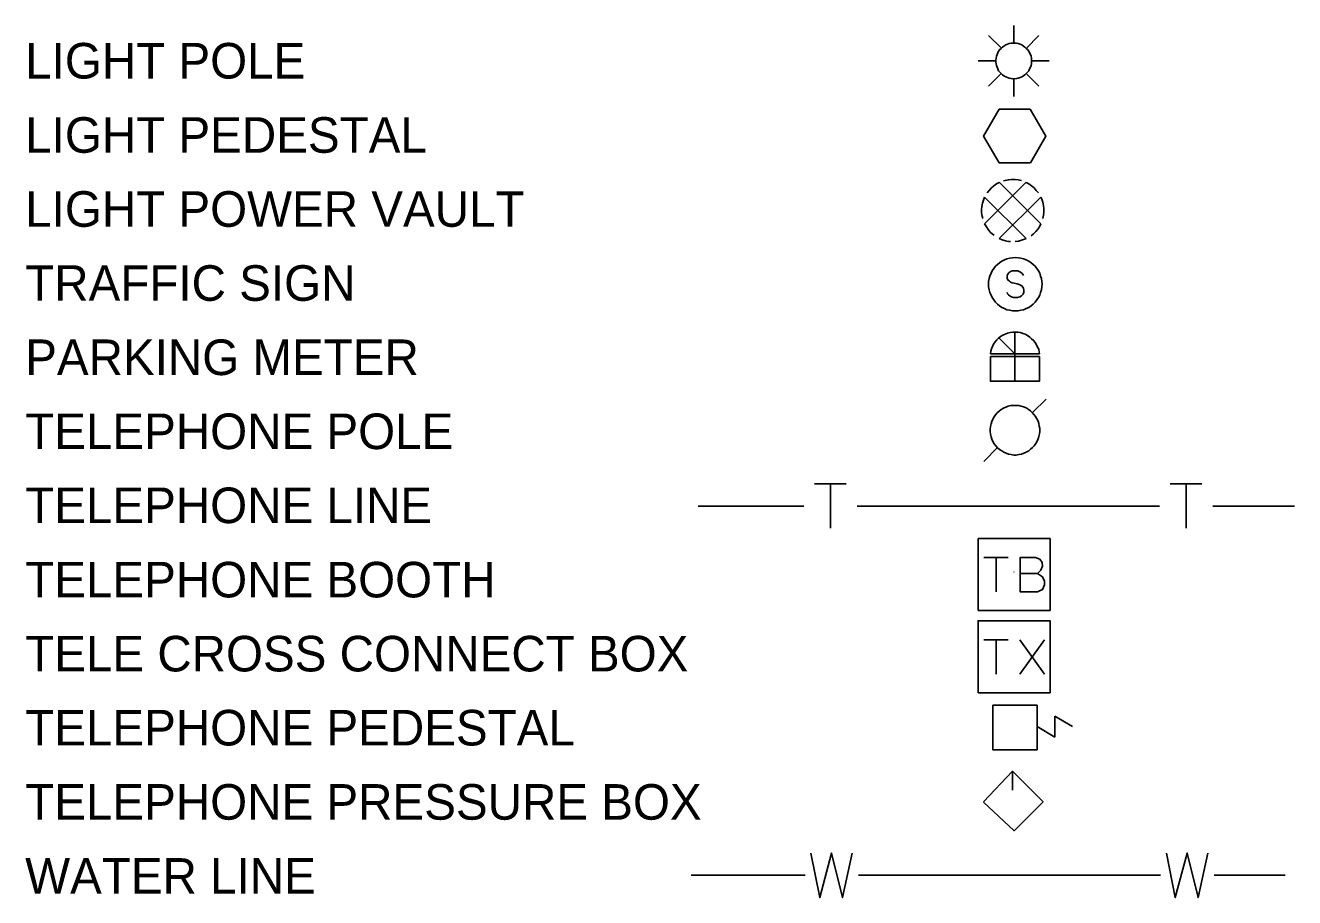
# Model space of a CAD drawing. Extents: x -1.93 to 2.83, y -1.79 to 1.85.
# Drawn here: x 0.5147 to 0.7634, y 1.1397 to 1.3106 of the extents above; entities that cross this region are included whole.
import ezdxf

# ---------------------------------------------------------------- set-up
doc = ezdxf.new("R2010")
doc.units = 0
doc.layers.add('Legend', color=7, linetype='Continuous')

msp = doc.modelspace()

# ---------------------------------------------------------------- linework, layer by layer
at = {"layer": 'Legend'}
for p, q in [((0.64654, 1.21642), (0.66721, 1.21642)), ((0.67766, 1.21642), (0.73691, 1.21642)), ((0.74733, 1.21642), (0.76337, 1.21642)), ((0.64512, 1.1441), (0.66746, 1.1441)), ((0.67791, 1.1441), (0.73712, 1.1441)), ((0.74758, 1.1441), (0.76154, 1.1441))]:
    msp.add_line(p, q, dxfattribs=at)
for points in [[(0.70835, 1.30711), (0.70835, 1.31057)], [(0.70589, 1.30615), (0.70339, 1.30857)], [(0.71081, 1.30607), (0.71327, 1.30857)], [(0.71081, 1.30607), (0.71052, 1.30632), (0.71023, 1.30653), (0.70993, 1.30674), (0.7096, 1.30686), (0.70923, 1.30699), (0.70889, 1.30707), (0.70852, 1.30711), (0.70814, 1.30711), (0.70781, 1.30707), (0.70743, 1.30699), (0.7071, 1.30686), (0.70677, 1.30674), (0.70643, 1.30653), (0.70614, 1.30632), (0.70585, 1.30607), (0.70564, 1.30582), (0.70539, 1.30553), (0.70523, 1.30519), (0.7051, 1.30486), (0.70498, 1.30453), (0.70489, 1.30415), (0.70485, 1.30378), (0.70485, 1.30344), (0.70489, 1.30307), (0.70498, 1.30269), (0.7051, 1.30236), (0.70523, 1.30203), (0.70539, 1.30169), (0.70564, 1.3014), (0.70585, 1.30115), (0.70614, 1.3009), (0.70643, 1.30069), (0.70677, 1.30049), (0.7071, 1.30036), (0.70743, 1.30024), (0.70781, 1.30015), (0.70814, 1.30011), (0.70852, 1.30011), (0.70889, 1.30015), (0.70923, 1.30024), (0.7096, 1.30036), (0.70993, 1.30049), (0.71023, 1.30069), (0.71052, 1.3009), (0.71081, 1.30115), (0.71106, 1.3014), (0.71127, 1.30169), (0.71143, 1.30203), (0.7116, 1.30236), (0.71173, 1.30269), (0.71181, 1.30307), (0.71181, 1.30344), (0.71181, 1.30378), (0.71181, 1.30415), (0.71173, 1.30453), (0.7116, 1.30486), (0.71143, 1.30519), (0.71127, 1.30553), (0.71106, 1.30582), (0.71081, 1.30607)], [(0.70139, 1.30361), (0.70489, 1.30361)], [(0.71181, 1.30361), (0.71531, 1.30361)], [(0.70589, 1.30115), (0.70339, 1.29869)], [(0.71081, 1.30115), (0.71327, 1.29869)], [(0.70835, 1.29665), (0.70835, 1.30015)], [(0.70552, 1.29417), (0.71156, 1.29417), (0.71464, 1.28887), (0.7116, 1.28362), (0.70552, 1.28362), (0.70243, 1.28887), (0.70552, 1.29417)], [(0.71081, 1.27984), (0.70264, 1.27167)], [(0.70552, 1.2798), (0.70498, 1.27951), (0.70443, 1.27913), (0.70398, 1.27872), (0.70352, 1.27826), (0.70314, 1.27776)], [(0.70552, 1.27984), (0.71368, 1.27167)], [(0.70985, 1.28017), (0.70923, 1.2803), (0.7086, 1.28038), (0.70793, 1.28038), (0.70731, 1.28034), (0.70668, 1.28022), (0.70631, 1.28013)], [(0.71318, 1.27776), (0.71277, 1.27826), (0.71235, 1.27872), (0.71185, 1.27913), (0.71131, 1.27951), (0.71077, 1.2798)], [(0.70264, 1.27692), (0.70239, 1.27634), (0.70223, 1.27572), (0.7021, 1.27509), (0.70206, 1.27447), (0.70206, 1.27384), (0.70214, 1.27322), (0.70227, 1.27272)], [(0.70264, 1.27692), (0.71081, 1.2688)], [(0.71368, 1.27692), (0.70552, 1.2688)], [(0.71406, 1.27276), (0.71418, 1.27338), (0.71423, 1.27401), (0.71423, 1.27463), (0.71418, 1.2753), (0.71402, 1.27592), (0.71385, 1.27651), (0.71364, 1.27692)], [(0.70264, 1.27167), (0.70298, 1.27109), (0.70331, 1.27059), (0.70373, 1.27009), (0.70418, 1.26967), (0.70448, 1.26947)], [(0.71173, 1.26938), (0.71223, 1.26976), (0.71268, 1.27022), (0.7131, 1.27072), (0.71343, 1.27126), (0.71364, 1.27167)], [(0.70552, 1.2688), (0.7061, 1.26855), (0.70673, 1.26838), (0.70735, 1.26826), (0.70768, 1.26822)], [(0.70864, 1.26822), (0.70927, 1.2683), (0.70989, 1.26847), (0.71048, 1.26867), (0.71077, 1.2688)], [(0.70864, 1.26509), (0.7081, 1.26505), (0.70756, 1.26497), (0.70702, 1.26484), (0.70652, 1.26463), (0.70602, 1.26438), (0.70556, 1.26409), (0.70514, 1.26376), (0.70477, 1.26338), (0.70443, 1.26292), (0.70414, 1.26247), (0.70389, 1.26201), (0.70368, 1.26147), (0.70356, 1.26097), (0.70343, 1.26042), (0.70343, 1.25988), (0.70343, 1.25934), (0.70356, 1.2588), (0.70368, 1.25826), (0.70389, 1.25776), (0.70414, 1.25726), (0.70443, 1.2568), (0.70477, 1.25638), (0.70514, 1.25597), (0.70556, 1.25563), (0.70602, 1.25534), (0.70652, 1.25509), (0.70702, 1.25488), (0.70756, 1.25476), (0.7081, 1.25467), (0.70864, 1.25463), (0.70918, 1.25467), (0.70973, 1.25476), (0.71027, 1.25488), (0.71077, 1.25509), (0.71127, 1.25534), (0.71173, 1.25563), (0.71214, 1.25597), (0.71252, 1.25638), (0.71289, 1.2568), (0.71318, 1.25726), (0.71343, 1.25776), (0.7136, 1.25826), (0.71377, 1.2588), (0.71385, 1.25934), (0.71389, 1.25988), (0.71385, 1.26042), (0.71377, 1.26097), (0.7136, 1.26147), (0.71343, 1.26201), (0.71318, 1.26247), (0.71289, 1.26292), (0.71252, 1.26338), (0.71214, 1.26376), (0.71173, 1.26409), (0.71127, 1.26438), (0.71077, 1.26463), (0.71027, 1.26484), (0.70973, 1.26497), (0.70918, 1.26505), (0.70864, 1.26509)], [(0.71023, 1.26155), (0.71018, 1.26172), (0.70998, 1.26197), (0.70964, 1.26226), (0.70914, 1.26247), (0.70877, 1.26251), (0.70835, 1.26251), (0.70806, 1.26247), (0.70768, 1.26234), (0.70739, 1.26213), (0.70714, 1.2618), (0.70706, 1.26142), (0.70706, 1.26105), (0.70718, 1.26072), (0.70752, 1.26047), (0.70773, 1.2603), (0.70806, 1.26017), (0.70843, 1.26005), (0.70902, 1.25992), (0.70943, 1.2598), (0.70993, 1.25955), (0.71023, 1.25909), (0.71031, 1.25867), (0.71031, 1.2583), (0.71018, 1.25792), (0.70985, 1.25763), (0.70952, 1.25742), (0.70906, 1.2573), (0.70873, 1.25726), (0.70831, 1.2573), (0.70789, 1.25738), (0.70764, 1.25755), (0.70731, 1.2578), (0.70714, 1.25797), (0.70706, 1.25822)], [(0.70377, 1.24624), (0.70385, 1.24674), (0.70398, 1.2472), (0.70418, 1.2477), (0.70439, 1.24812), (0.70468, 1.24857), (0.70502, 1.24895), (0.70539, 1.24928), (0.70577, 1.24962), (0.70623, 1.24991), (0.70668, 1.25012), (0.70714, 1.25028), (0.70764, 1.25041), (0.70814, 1.25049), (0.70864, 1.25049), (0.70914, 1.25049), (0.70964, 1.25041), (0.71014, 1.25024), (0.7106, 1.25007), (0.71106, 1.24982), (0.71148, 1.24953), (0.71185, 1.2492), (0.71223, 1.24887), (0.71252, 1.24845), (0.71281, 1.24803), (0.71302, 1.24757), (0.71323, 1.24712), (0.71335, 1.24662), (0.71339, 1.24624)], [(0.70856, 1.24624), (0.70543, 1.24937)], [(0.70856, 1.24093), (0.70856, 1.25049)], [(0.70377, 1.24624), (0.71339, 1.24624)], [(0.70377, 1.2457), (0.70377, 1.24087), (0.71339, 1.24087), (0.71339, 1.2457), (0.70377, 1.2457)], [(0.71198, 1.23475), (0.7116, 1.23509), (0.71118, 1.23538), (0.71077, 1.23563), (0.71027, 1.23584), (0.70981, 1.23596), (0.70931, 1.23609), (0.70881, 1.23613), (0.70831, 1.23613), (0.70777, 1.23609), (0.70727, 1.23596), (0.70681, 1.23579), (0.70635, 1.23559), (0.70589, 1.23534), (0.70548, 1.23504), (0.7051, 1.23467), (0.70477, 1.23429), (0.70448, 1.23388), (0.70423, 1.23346), (0.70402, 1.233), (0.70389, 1.2325), (0.70377, 1.232), (0.70373, 1.2315), (0.70373, 1.231), (0.70377, 1.2305), (0.70389, 1.23), (0.70406, 1.2295), (0.70427, 1.22904), (0.70452, 1.22863), (0.70481, 1.22821), (0.70518, 1.22784), (0.70556, 1.2275), (0.70598, 1.22721), (0.70639, 1.22696), (0.70685, 1.22675), (0.70735, 1.22659), (0.70785, 1.2265), (0.70835, 1.22642), (0.70885, 1.22642), (0.70935, 1.2265), (0.70985, 1.22659), (0.71035, 1.22675), (0.71081, 1.22696), (0.71127, 1.22721), (0.71164, 1.22754), (0.71202, 1.22788), (0.71235, 1.22825), (0.71268, 1.22867), (0.71293, 1.22913), (0.7131, 1.22959), (0.71327, 1.23004), (0.71339, 1.23054), (0.71343, 1.23104), (0.71343, 1.23159), (0.71335, 1.23209), (0.71327, 1.23259), (0.7131, 1.23304), (0.71289, 1.2335), (0.71264, 1.23396), (0.71231, 1.23438), (0.71198, 1.23475)], [(0.71468, 1.23738), (0.71202, 1.23475)], [(0.7051, 1.22784), (0.70248, 1.22517)], [(0.67244, 1.21209), (0.67244, 1.2208), (0.66929, 1.2208)], [(0.67244, 1.2208), (0.67553, 1.2208)], [(0.74211, 1.21209), (0.74211, 1.2208), (0.73896, 1.2208)], [(0.74211, 1.2208), (0.7452, 1.2208)], [(0.70139, 1.19597), (0.70139, 1.21005), (0.71548, 1.21005), (0.71548, 1.19597), (0.70139, 1.19597)], [(0.70493, 1.19964), (0.70493, 1.20634), (0.70248, 1.20634)], [(0.70493, 1.20634), (0.70727, 1.20634)], [(0.71298, 1.20322), (0.71364, 1.20384), (0.71398, 1.20464), (0.71389, 1.20539), (0.71343, 1.20601), (0.71264, 1.20634), (0.7096, 1.20634), (0.7096, 1.19964), (0.71298, 1.19964), (0.71398, 1.20005), (0.71439, 1.20097), (0.71439, 1.20172), (0.71398, 1.20255), (0.71298, 1.20322), (0.7096, 1.20322)], [(0.70135, 1.17985), (0.70135, 1.19397), (0.71548, 1.19397), (0.71548, 1.17985), (0.70135, 1.17985)], [(0.70489, 1.18352), (0.70489, 1.19022), (0.70248, 1.19022)], [(0.70489, 1.19022), (0.70723, 1.19022)], [(0.70956, 1.19022), (0.71435, 1.18352)], [(0.70956, 1.18352), (0.71435, 1.19022)], [(0.70423, 1.17741), (0.71293, 1.17741)], [(0.70423, 1.17741), (0.70423, 1.1687), (0.71293, 1.1687)], [(0.71293, 1.17741), (0.71293, 1.1687)], [(0.71639, 1.17524), (0.71639, 1.17116)], [(0.71985, 1.17324), (0.71639, 1.17524)], [(0.71639, 1.17116), (0.71293, 1.17324)], [(0.70239, 1.15848), (0.7081, 1.16448), (0.7141, 1.15848), (0.70843, 1.15281), (0.70239, 1.15844)], [(0.7081, 1.16448), (0.7081, 1.16077)], [(0.66862, 1.14844), (0.67034, 1.13973), (0.67267, 1.14844), (0.67479, 1.13973), (0.67671, 1.14844)], [(0.73829, 1.14844), (0.74, 1.13973), (0.74234, 1.14844), (0.74446, 1.13973), (0.74638, 1.14844)]]:
    msp.add_lwpolyline(points, dxfattribs=at)
msp.add_circle((0.70842, 1.20353), 0.000000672, dxfattribs=at)

# ---------------------------------------------------------------- texts
for s, height, p in [('LIGHT POLE', 0.006967, (0.51467, 1.30016)), ('LIGHT PEDESTAL', 0.0069667, (0.51467, 1.28562)), ('LIGHT POWER VAULT', 0.0069667, (0.51467, 1.27112)), ('TRAFFIC SIGN', 0.0069667, (0.51467, 1.25662)), ('PARKING METER', 0.0069667, (0.51467, 1.24208)), ('TELEPHONE POLE', 0.0069667, (0.51467, 1.22758)), ('TELEPHONE LINE', 0.0069667, (0.51467, 1.21308)), ('TELEPHONE BOOTH', 0.0069667, (0.51467, 1.19853)), ('TELE CROSS CONNECT BOX', 0.0069667, (0.51467, 1.18403)), ('TELEPHONE PEDESTAL', 0.0069667, (0.51467, 1.16953)), ('TELEPHONE PRESSURE BOX', 0.0069667, (0.51467, 1.15499)), ('WATER LINE', 0.006967, (0.51467, 1.14049))]:
    msp.add_text(s, height=height, dxfattribs=at).set_placement(p)

doc.saveas('drawing.dxf')
